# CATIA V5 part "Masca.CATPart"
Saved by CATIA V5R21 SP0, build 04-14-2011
Part number: Masca
Bounding box of the stored display mesh (mm): x -30 to 30, y -44 to 30, z -114 to 759.5
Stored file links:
  C:\Users\MIRCEA\Desktop\PRRO\CATIAV5\Masca.CATPart
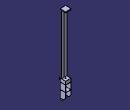
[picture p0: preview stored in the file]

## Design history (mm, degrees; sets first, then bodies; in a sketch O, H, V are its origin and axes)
Body1 (main body)
  Plane1: type Offset, RefPlane xy-plane, Offset 76
  Sketch1 on Plane1, origin (0, 0, 76), H (1, 0, 0), V (0, 1, 0)
    line L1 (30, 30) -> (30, -30)
    line L2 (30, -30) -> (-30, -30)
    line L3 (-30, -30) -> (-30, 30)
    line L4 (-30, 30) -> (30, 30)
    point P1 (30, 30)
    circle A1 centre (0, 0) radius 4.5
    distance P1 H = 30
    distance P1 V = 30
    radius A1 = 4.5
    vertical: L1 V, L3 V
    horizontal: L2 H, L4 H
    equidistance: L1 L3 O, L2 L4 O
  Pad1: profile Sketch1, direction (0, 0, -1), length 3
  Sketch2 on Plane1, origin (0, 0, 76), H (1, 0, 0), V (0, 1, 0)
    point P1 (-0.3803, 0)
    line L1 (28, 28) -> (28, -28)
    line L2 (28, -28) -> (-28.7607, -28)
    line L3 (-28.7607, -28) -> (-28.7607, 28)
    line L4 (-28.7607, 28) -> (28, 28)
    point P2 (28, 28)
    line L5 (30, 30) -> (30, -30)
    line L6 (30, -30) -> (-30, -30)
    line L7 (-30, -30) -> (-30, 30)
    line L8 (-30, 30) -> (30, 30)
    point P6 (30, 30)
    distance P2 H = 28
    distance P2 V = 28
    distance P6 H = 30
    distance P6 V = 30
    coincidence: P1 H
    vertical: L1 V, L3 V, L5 V, L7 V
    horizontal: L2 H, L4 H, L6 H, L8 H
    equidistance: L1 L3 P1, L2 L4 P1, L5 L7 O, L6 L8 O
  Pad2: profile Sketch2, direction (0, 0, 1), length 33
  Plane2: type Offset, RefPlane Plane1, Offset 33
  Sketch3 on Plane2, origin (0, 0, 109), H (1, 0, 0), V (0, 1, 0)
    circle A1 centre (0, 0) radius 6
    line L1 (30, 30) -> (30, -30)
    line L2 (30, -30) -> (-30, -30)
    line L3 (-30, -30) -> (-30, 30)
    line L4 (-30, 30) -> (30, 30)
    point P1 (30, 30)
    radius A1 = 6
    distance P1 V = 30
    distance P1 H = 30
    vertical: L1 V, L3 V
    horizontal: L2 H, L4 H
    equidistance: L1 L3 O, L2 L4 O
  Pad3: profile Sketch3, direction (0, 0, 1), length 1.5
  Plane3: type Offset, RefPlane zx-plane, Offset -30
  Sketch4 on Plane3, origin (0, -30, 0), H (-1, 0, 0), V (0, 0, 1)
    circle A1 centre (0, 95) radius 14
    radius A1 = 14
  Pad4: profile Sketch4, direction (0, -1, 0), length 10
  Plane4: type Offset, RefPlane Plane3, Offset -10
  Sketch5 on Plane4, origin (0, -40, 0), H (-1, 0, 0), V (0, 0, 1)
    circle A1 centre (0, 95) radius 25
    radius A1 = 25
  Pad5: profile Sketch5, direction (0, -1, 0), length 4
  Sketch6 on Plane2, origin (0, 0, 109), H (1, 0, 0), V (0, 1, 0)
    line L1 (0, -15) -> (30, -15)
    line L2 (30, -15) -> (30, -30)
    line L3 (30, -30) -> (-30, -30)
    line L4 (-30, -30) -> (-30, -15)
    point P5 (-30, -15)
    line L5 (0, -15) -> (-30, -15)
    length L1 = 30
    length L2 = 15
    length L3 = 60
    horizontal: L1 H, L3 H, L5 H
    vertical: L2 V, L4 V
    coincidence: P5 L1
  Pad6: profile Sketch6, direction (0, 0, 1), length 640.5
  Plane5: type Offset, RefPlane Plane2, Offset 640.5
  Sketch7 on Plane5, origin (0, 0, 749.5), H (1, 0, 0), V (0, 1, 0)
    line L1 (30, 30) -> (30, -30)
    line L2 (30, -30) -> (-30, -30)
    line L3 (-30, -30) -> (-30, 30)
    line L4 (-30, 30) -> (30, 30)
    point P1 (30, 30)
    distance P1 H = 30
    distance P1 V = 30
    vertical: L1 V, L3 V
    horizontal: L2 H, L4 H
    equidistance: L1 L3 O, L2 L4 O
  Pad7: profile Sketch7, direction (0, 0, 1), length 10
  Sketch8 on Plane1, origin (0, 0, 76), H (1, 0, 0), V (0, 1, 0)
    point P1 (0, -29.5)
    line L1 (30, -28.75) -> (30, -30.25)
    line L2 (30, -30.25) -> (-30, -30.25)
    line L3 (-30, -30.25) -> (-30, -28.75)
    line L4 (-30, -28.75) -> (30, -28.75)
    distance L2 L4 = 1.5
    distance L1 L3 = 60
    vertical: L1 V, L3 V
    horizontal: L2 H, L4 H
    equidistance: L1 L3 P1, L2 L4 P1
  Pad8: profile Sketch8, direction (0, 0, -1), length 190
  Plane6: type Offset, RefPlane yz-plane, Offset 30
  Plane7: type Offset, RefPlane yz-plane, Offset -30
  Sketch9 on Plane7, origin (-30, 0, 0), H (0, 1, 0), V (0, 0, 1)
    line L1 (30, 75) -> (30, -75)
    line L2 (30, -75) -> (-30, -75)
    line L3 (-30, -75) -> (-30, 75)
    line L4 (-30, 75) -> (30, 75)
    distance L2 L4 = 150
    distance L1 L3 = 60
    vertical: L1 V, L3 V
    horizontal: L2 H, L4 H
    equidistance: L1 L3 O, L2 L4 O
  Pad9: profile Sketch9, direction (1, 0, 0), length 1.5
  Sketch10 on Plane6, origin (30, 0, 0), H (0, 1, 0), V (0, 0, 1)
    line L1 (30, 75) -> (30, -75)
    line L2 (30, -75) -> (-30, -75)
    line L3 (-30, -75) -> (-30, 75)
    line L4 (-30, 75) -> (30, 75)
    distance L2 L4 = 150
    distance L1 L3 = 60
    vertical: L1 V, L3 V
    horizontal: L2 H, L4 H
    equidistance: L1 L3 O, L2 L4 O
  Pad10: profile Sketch10, direction (-1, 0, 0), length 1.5
  Chamfer1: length 25, angle 45, on edge [face of Pad10 from Sketch10.L2 | face of Pad10]; edge [face of Pad10 | face of Pad9 from Sketch9.L2]; edge [end face of Pad8 | face of Pad9]; edge [end face of Pad8 | face of Pad10]
  Plane8: type Offset, RefPlane xy-plane, Offset -111
  Plane9: type Offset, RefPlane xy-plane, Offset 1.25
  Sketch11 on Plane9, origin (0, 0, 1.25), H (1, 0, 0), V (0, 1, 0)
    line L1 (30, 30) -> (30, -30)
    line L2 (30, -30) -> (-30, -30)
    line L3 (-30, -30) -> (-30, 30)
    line L4 (-30, 30) -> (30, 30)
    point P1 (30, 30)
    distance P1 V = 30
    distance P1 H = 30
    vertical: L1 V, L3 V
    horizontal: L2 H, L4 H
    equidistance: L1 L3 O, L2 L4 O
  Pad11: profile Sketch11, direction (0, 0, 1), length 3.5
  Sketch12 on Plane9, origin (0, 0, 1.25), H (1, 0, 0), V (0, 1, 0)
    circle A1 centre (23.5, 23.5) radius 2.5
    circle A2 centre (-23.5, 23.5) radius 2.5
    circle A3 centre (23.5, -23.5) radius 2.5
    circle A4 centre (-23.5, -23.5) radius 2.5
    radius A1 = 2.5
    radius A2 = 2.5
    radius A3 = 2.5
    radius A4 = 2.5
  Pocket1: profile Sketch12, direction (0, 0, 1), through (limit type 6)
